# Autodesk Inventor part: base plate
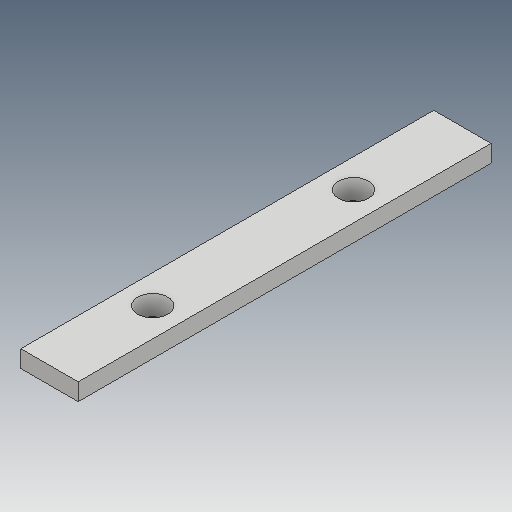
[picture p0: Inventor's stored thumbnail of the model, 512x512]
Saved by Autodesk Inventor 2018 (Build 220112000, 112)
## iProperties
Created: 2016-03
Part Number: base plate
Material: Generic
Document SubType Name: Modeling
Designer: Sandeep
Density: 1 g/cm^3
Appearance: Default
Mass: 16.6527 g
Surface Area: 78.2446 cm^2
Volume: 16.6527 cm^3
Author: Sandeep
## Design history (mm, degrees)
sketch "Sketch1"
  geometry: L1 (0, 0)-(144, 0); L2 (144, 0)-(144, 20); L3 (144, 20)-(0, 20); L4 (0, 20)-(0, 0)
  constraints: 8 end point, 2 parallel, 1 horizontal, 1 perpendicular
  dimensions: "d0" = 144 distance of L1.start L1.end; "d1" = 20 distance of L1.end L2.end
extrude "Extrusion1" new body sketch "Sketch1" distance "d2" = 6; taper "d3" = 0 deg
sketch "Sketch2"
  geometry: L1 (0, 20)-(0, 0) reference; L2 (0, 10)-(181.292, 10); 2 further points
  constraints: 2 end point, 2 point on line, 1 horizontal, 1 midpoint
  dimensions: "d4" = 70 distance of point (108, 10) point (38, 10); "d5" = 38 distance from line of L1 point (38, 10)
hole "Hole1" sketch "Sketch2" at (38, 10), (108, 10) diameter "d6" = 6; stored, may be unused: countersink angle "d10" = 45 deg, drill point angle "d12" = 118 deg; dims "d7" = 6, "d8" = 10.5, "d9" = 2, "d11" = 8
body "Solid1"
